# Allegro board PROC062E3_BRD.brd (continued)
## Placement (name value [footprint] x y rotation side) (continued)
NOREF#13  -  [#2]  213.87 20.07 0 top
NOREF#14  -  [unnamed]  206.38 143.51 0 top
NOREF#15  -  [unnamed]  3.49 4.19 0 top
NOREF#16  -  [unnamed]  10.79 72.99 0 top
NOREF#17  -  [#2]  -497.2 -71.75 0 top
NOREF#18  -  [#2]  11.81 0 90 top
NOREF#19  -  [unnamed]  87.71 3.81 0 top
NOREF#20  -  [#2]  98.62 -83.11 0 top
NOREF#21  -  [unnamed]  10.79 7.62 0 top
NOREF#22  -  [#2]  38.73 -95.89 0 top
NOREF#23  -  [unnamed]  206.38 170.05 0 top
NOREF#24  -  [unnamed]  164.53 143.51 0 top
NOREF#25  -  [unnamed]  206.38 106.68 0 top
NOREF#26  -  [unnamed]  213.68 4.19 0 top
NOREF#27  -  [#2]  330.6 97.43 0 top
NOREF#28  -  [unnamed]  146.43 43.18 0 top
NOREF#29  -  [unnamed]  3.49 9.14 0 top
NOREF#30  -  [unnamed]  192.15 26.04 0 top
NOREF#31  -  [unnamed]  10.79 170.05 0 top
NOREF#32  -  [unnamed]  197.87 73.03 0 top
NOREF#33  -  [unnamed]  10.79 173.99 0 top
NOREF#34  -  [unnamed]  114.36 143.51 0 top
NOREF#35  -  [unnamed]  193.68 3.81 0 top
NOREF#36  -  [unnamed]  213.68 173.61 0 top
NOREF#37  -  [unnamed]  105.47 173.99 0 top
NOREF#38  -  [#2]  -123.44 -23.24 0 top
NOREF#39  -  [unnamed]  173.36 1.97 0 top
NOREF#40  -  [unnamed]  10.79 3.81 0 top
NOREF#41  -  [unnamed]  3.49 173.61 0 top
NOREF#42  -  [unnamed]  149.36 1.97 0 top
NOREF#43  -  [unnamed]  3.49 168.4 180 bottom
NOREF#44  -  [unnamed]  206.38 170.05 180 bottom
NOREF#45  -  [unnamed]  3.49 9.14 180 bottom
NOREF#46  -  [unnamed]  10.79 7.62 180 bottom
NOREF#47  -  [unnamed]  213.68 168.4 180 bottom
NOREF#48  -  [unnamed]  10.79 170.05 180 bottom
Q1  SUM60N10-17-E3  [D2PAK-3]  45.47 149.22 270 top
Q2  SUM60N10-17-E3  [D2PAK-3]  43.43 137.16 90 top
Q3  BSS138LT1G  [SOT23-123]  15.49 132.61 270 top
Q4  BSS138LT1G  [SOT23-123]  11.91 130.57 270 top
Q5  BSS138LT1G  [SOT23-123]  18.84 104.03 270 top
Q6  BSS138LT1G  [SOT23-123]  22.99 76.58 180 top
Q7  IRLML6401  [TO_SOT23-123]  107.13 30.26 180 top
Q8  BSS138  [TO_SOT23-123]  22.86 166.62 90 bottom
Q9  BSS138LT1G  [SOT23-123]  12.41 109.37 0 bottom
Q10  BSS138LT1G  [SOT23-123]  72.12 107.13 90 bottom
Q11  BSS138LT1G  [SOT23-123]  63.46 103.25 90 bottom
Q12  BSS138LT1G  [SOT23-123]  25.48 99.46 270 bottom
Q13  BSS138LT1G  [SOT23-123]  21.67 99.45 270 bottom
Q14  BSS138LT1G  [SOT23-123]  13.31 93.93 0 bottom
Q15  BSS138LT1G  [SOT23-123]  21.73 84.35 180 bottom
Q16  BSS138LT1G  [SOT23-123]  13.49 88.97 0 bottom
Q17  BSS138LT1G  [SOT23-123]  22.99 76.58 180 bottom
R1  220E  [RES0402_0-5]  77.36 173.26 90 top
R2  1K  [RES0201]  85.66 173.16 90 top
R3  220E  [RES0402_0-5]  81.61 173.11 90 top
R4  1K  [RES0201]  143.92 173.61 0 top
R5  10K  [RES1206]  16.26 172.91 90 top
R6  10K  [RES0402_0-5]  127.25 168.77 270 top
R7  10K  [RES0402_0-5]  143.64 170.78 270 top
R8  10K  [RES0402_0-5]  136.82 170.43 0 top
R9  1K  [RES0201]  21.87 170.08 90 top
R10  0E  [RES0402_0-5]  138.37 170.01 270 top
R11  1K  [RES0201]  143.92 169.04 0 top
R12  100K  [RES0402_0-5]  165.23 168.31 90 top
R13  10K  [RES1206]  13.92 168.25 270 top
R14  0E  [RES0402_0-5]  156.27 167.68 0 top
R15  20.5K  [RES0402]  167.74 167.2 0 top
R16  10.2K_0.1%  [RES0402]  167.74 166.18 180 top
R17  1M  [RES0603_0-75]  12.8 166.09 180 bottom
R18  0E  [RES0402_0-5]  181.89 160.43 180 top
R19  10K  [RES0402_0-5]  155.58 158.96 90 top
R20  10K  [RES0402_0-5]  156.59 158.96 90 top
R21  10K  [RES0402_0-5]  157.61 158.96 270 top
R22  10K  [RES0402_0-5]  158.62 158.96 270 top
R23  10K  [RES0402_0-5]  159.64 158.96 270 top
R24  10K  [RES0402_0-5]  160.66 158.96 270 top
R25  16K_1%  [RES0402]  17.35 156.54 0 top
R26  10K  [RES0402_0-5]  136.39 156.51 180 top
R27  10K  [RES0402_0-5]  146.18 156.09 0 top
R28  76.8K_1%  [RES0402]  17.35 155.53 180 top
R29  10K  [RES0402_0-5]  136.39 155.5 180 top
R30  10K  [RES0402_0-5]  124.55 155.46 0 top
R31  10K_1%  [RES0402_0-5]  117.38 155.09 90 top
R32  10K  [RES0402_0-5]  124.55 154.48 0 top
R33  10K  [RES0402_0-5]  145.42 136.78 270 bottom
R34  23.2K_1%  [RES0402]  17.35 154.48 0 top
R35  10K_1%  [RES0402_0-5]  116.37 153.84 270 top
R36  10K  [RES0402_0-5]  136.39 154.14 180 top
R37  10K  [RES0402_0-5]  20.38 152.33 90 top
R38  10K  [RES0402_0-5]  159.26 149.86 180 top
R39  49.9E_1%  [RES0201]  135.86 149.95 180 top
R40  49.9E_1%  [RES0201]  137.22 149.95 0 top
R41  100K  [RES0402_0-5]  205.93 150.7 0 top
R42  10K_1%  [RES0402_0-5]  117.38 148.58 90 top
R43  39.2E_1%  [RES0402]  189.93 148.08 90 top
R44  39.2E_1%  [RES0402]  191.96 148.08 90 top
R45  39.2E_1%  [RES0402]  185.86 148.08 90 top
R46  39.2E_1%  [RES0402]  186.88 148.08 90 top
R47  39.2E_1%  [RES0402]  187.9 148.08 90 top
R48  39.2E_1%  [RES0402]  188.91 148.08 90 top
R49  39.2E_1%  [RES0402]  190.94 148.08 90 top
R50  10K  [RES0402_0-5]  20.38 147.97 90 top
R51  10K_1%  [RES0402_0-5]  116.37 147.33 270 top
R52  240E_1%  [RES0402]  181.5 145.16 180 top
R53  1K_1%  [RES0402_0-5]  81.47 144.65 180 top
R54  8.66K_1%  [RES0402]  81.47 143.64 0 top
R55  46.4K_1%  [RES0402]  78.74 142.88 0 top
R56  39.2E_1%  [RES0402]  195.07 142.75 0 top
R57  39.2E_1%  [RES0402]  195.07 141.73 0 top
R58  10K  [RES0402_0-5]  145.37 141.17 270 top
R59  49.9E_1%  [RES0201]  134.91 142.28 180 top
R60  49.9E_1%  [RES0201]  136.57 142.28 0 top
R61  39.2E_1%  [RES0402]  195.07 140.72 0 top
R62  0.028E_2%  [RES0815_0-75]  88.27 140.46 90 top
R63  39.2E_1%  [RES0402]  195.07 139.7 0 top
R64  10K_1%  [RES0402_0-5]  78.49 139.45 0 top
R65  18.2K_1%  [RES0402]  81.03 139.45 180 top
R66  10K  [RES0402_0-5]  157.29 139.13 180 top
R67  39.2E_1%  [RES0402]  195.07 138.68 0 top
R68  75K_1%  [RES0402_0-5]  78.49 138.43 180 top
R69  39.2E_1%  [RES0402]  195.07 136.65 0 top
R70  39.2E_1%  [RES0402]  195.07 135.64 0 top
R71  1M  [RES0603_0-75]  11.43 145.67 180 bottom
R72  0E  [RES0402_0-5]  12.44 132.84 180 top
R73  0E  [RES0402_0-5]  17.91 133.24 270 top
R74  0E  [RES0402_0-5]  122.11 129.54 0 top
R75  240E_1%  [RES0402]  181.5 131.44 180 top
R76  0E  [RES0402_0-5]  122.11 128.4 0 top
R77  1K  [RES0201]  8.36 130.2 90 top
R78  220E  [RES0402_0-5]  9.4 129.94 90 top
R79  220E  [RES0402_0-5]  15.91 129.67 0 top
R80  10K_1%  [RES0402_0-5]  113.28 127.87 90 top
R81  10K  [RES0402_0-5]  138.62 127.19 90 top
R82  10K  [RES0402_0-5]  139.64 127.19 270 top
R83  100K  [RES0402_0-5]  140.65 127.19 90 top
R84  1K  [RES0402]  141.67 127.19 270 top
R87  10K  [RES0402_0-5]  144.72 127.19 270 top
R88  10K  [RES0402_0-5]  145.73 127.19 90 top
R89  10K_1%  [RES0402_0-5]  112.28 126.62 270 top
R90  10K_1%  [RES0402_0-5]  33.27 123.44 270 top
R91  2.49K_1%  [RES0402]  34.29 123.44 90 top
R92  2.49K_1%  [RES0402]  35.31 123.44 90 top
R93  10K_1%  [RES0402_0-5]  36.32 123.44 270 top
R94  5.76K_1%  [RES0402]  37.47 123.44 270 top
R95  2.49K_1%  [RES0402]  38.48 123.44 90 top
R96  2.49K_1%  [RES0402]  39.5 123.44 90 top
R97  10K_1%  [RES0402_0-5]  40.51 123.44 270 top
R98  5.76K_1%  [RES0402]  41.53 123.44 90 top
R99  2.49K_1%  [RES0402]  42.55 123.44 90 top
R100  2.2K  [RES0402_0-5]  35.69 120.9 90 top
R101  22E_1%  [RES0402]  40.39 120.9 270 top
R102  22E_1%  [RES0402]  42.67 120.27 180 top
R103  220E  [RES0402_0-5]  48.01 119.89 270 top
R104  220E  [RES0402_0-5]  50.8 119.89 270 top
R105  220E  [RES0402_0-5]  53.57 119.89 270 top
R106  220E  [RES0402_0-5]  56.39 119.89 270 top
R107  220E  [RES0402_0-5]  59.05 119.89 270 top
R108  220E  [RES0402_0-5]  61.85 119.89 270 top
R109  220E  [RES0402_0-5]  64.77 119.89 270 top
R110  220E  [RES0402_0-5]  67.44 119.89 270 top
R111  22E_1%  [RES0402]  42.67 119.13 180 top
R112  2.49K_1%  [RES0402]  45.47 119.13 0 top
R113  10K_1%  [RES0402_0-5]  108.82 119.09 180 top
R114  22E_1%  [RES0402]  42.67 118.11 180 top
R115  2.49K_1%  [RES0402]  45.47 118.11 180 top
R116  10K_1%  [RES0402_0-5]  110.07 118.08 0 top
R117  240E_1%  [RES0402]  181.5 117.73 180 top
R118  22E_1%  [RES0402]  42.67 116.97 180 top
R119  2.49K_1%  [RES0402]  45.47 116.97 180 top
R120  10K  [RES0402_0-5]  108.01 116.03 0 top
R121  22E_1%  [RES0402]  42.67 115.95 180 top
R122  2.49K_1%  [RES0402]  45.47 115.95 0 top
R123  10K  [RES0402_0-5]  105.6 115.57 0 top
R124  10K  [RES0402_0-5]  96.18 115.49 180 top
R125  10K  [RES0402_0-5]  108.01 115.05 180 top
R126  10K  [RES0402_0-5]  105.6 114.55 0 top
R127  10K  [RES0402_0-5]  96.18 114.49 180 top
R128  33E_1%  [RES0402_0-5]  139.45 114.43 90 top
R129  0E  [RES0402_0-5]  140.46 114.43 90 top
R130  4.7K  [RES0402]  141.48 114.43 90 top
R131  33E_1%  [RES0402_0-5]  144.21 114.43 270 top
R132  22E_1%  [RES0402]  150.81 114.36 270 top
R133  10K  [RES0402_0-5]  105.6 113.54 0 top
R134  10K  [RES0402_0-5]  92.03 112.72 270 top
R135  11K_1%  [RES0402_0-5]  31.88 112.64 180 top
R136  100K  [RES0402_0-5]  105.6 112.52 0 top
R137  10K_1%  [RES0402_0-5]  48.13 110.29 270 top
R138  2.49K_1%  [RES0402]  49.15 110.29 90 top
R139  2.49K_1%  [RES0402]  50.16 110.29 90 top
R140  10K_1%  [RES0402_0-5]  51.18 110.29 270 top
R141  5.76K_1%  [RES0402]  52.2 110.29 270 top
R142  2.49K_1%  [RES0402]  53.21 110.29 90 top
R143  2.49K_1%  [RES0402]  54.23 110.29 90 top
R144  10K_1%  [RES0402_0-5]  55.24 110.29 270 top
R145  5.76K_1%  [RES0402]  56.26 110.29 90 top
R146  2.49K_1%  [RES0402]  57.28 110.29 90 top
R147  10K_1%  [RES0402_0-5]  110.3 109.06 180 top
R148  0E  [RES0402_0-5]  111.84 108.64 90 top
R149  10K  [RES0201]  32.28 108.03 270 top
R150  10K  [RES0402_0-5]  31.24 107.82 270 top
R151  2.2K  [RES0402_0-5]  50.42 107.75 90 top
R152  22E_1%  [RES0402]  55.12 107.75 270 top
R153  10K  [RES0402_0-5]  99.35 107.53 180 top
R154  22E_1%  [RES0402]  57.4 107.12 180 top
R155  220E  [RES0402_0-5]  71.04 106.81 90 top
R156  10K  [RES0201]  35.91 106.17 0 top
R157  22E_1%  [RES0402]  57.4 105.97 180 top
R158  2.49K_1%  [RES0402]  60.2 105.97 0 top
R159  10K  [RES0402_0-5]  105.34 105.63 0 top
R160  10K  [RES0402_0-5]  35.91 105.15 0 top
R161  0E  [RES0402_0-5]  21.77 105.08 0 top
R162  22E_1%  [RES0402]  57.4 104.96 180 top
R163  2.49K_1%  [RES0402]  60.2 104.96 180 top
R164  10K  [RES0402_0-5]  29.34 104.65 0 top
R165  0E  [RES0402_0-5]  164.21 104.39 180 top
R166  240E_1%  [RES0402]  181.5 104.01 180 top
R167  2.49K_1%  [RES0402]  60.2 103.94 180 top
R168  22E_1%  [RES0402]  57.4 103.82 180 top
R169  22E_1%  [RES0402]  72.64 103.38 90 top
R170  22E_1%  [RES0402]  73.66 103.38 90 top
R171  0E  [RES0402_0-5]  164.21 103.38 180 top
R172  1K  [RES0201]  76.05 103.37 90 top
R173  1K  [RES0201]  77.58 103.37 270 top
R174  10K  [RES0201]  37.51 103.25 0 top
R175  10K  [RES0201]  32.57 103.96 180 bottom
R176  10K  [RES0402_0-5]  91.23 103.06 270 top
R177  220E  [RES0402_0-5]  64.58 102.99 90 top
R178  220E  [RES0402_0-5]  15.88 102.98 180 top
R179  2.49K_1%  [RES0402]  60.2 102.93 0 top
R180  0E  [RES0402_0-5]  118.45 102.87 180 top
R181  22E_1%  [RES0402]  57.4 102.8 180 top
R182  2.2K  [RES0402_0-5]  164.21 102.36 0 top
R183  0E  [RES0402_0-5]  118.45 101.85 180 top
R184  100E  [RES0402_0-5]  107.38 101.77 90 top
R185  100E  [RES0402_0-5]  75.78 100.62 270 top
R186  240E_1%  [RES0402]  164.21 100.33 0 top
R187  10K  [RES0402_0-5]  66.8 100.09 0 top
R188  11K_1%  [RES0402_0-5]  46.61 99.49 180 top
R189  10K  [RES0402_0-5]  66.8 99.07 180 top
R190  100E  [RES0402_0-5]  76.2 99.06 0 top
R191  0E  [RES0402_0-5]  78.17 98.78 180 top
R192  1M_1%  [RES0402]  79.69 98.18 90 top
R193  10K  [RES0402_0-5]  66.8 98.06 180 top
R194  0E  [RES0402_0-5]  78.17 97.57 180 top
R195  0E  [RES0402_0-5]  107.37 97.39 270 top
R196  10E_1%  [RES0402_0-5]  96.39 97.35 0 top
R197  10K  [RES0402_0-5]  66.8 97.04 0 top
R198  2.2K  [RES0402_0-5]  50.16 97.03 180 top
R199  10K  [RES0402_0-5]  66.8 96.02 180 top
R200  261K_1%  [RES0402_0-5]  89.93 95.4 270 top
R201  10K_1%  [RES0402_0-5]  90.95 95.4 90 top
R202  10E_1%  [RES0402_0-5]  96.1 95 180 top
R203  22E_1%  [RES0402]  68.45 94.11 270 top
R204  22E_1%  [RES0402]  71.12 94.11 270 top
R205  22E_1%  [RES0402]  72.14 94.11 270 top
R206  22E_1%  [RES0402]  73.15 94.11 270 top
R207  22E_1%  [RES0402]  74.17 94.11 270 top
R208  22E_1%  [RES0402]  164.13 92.7 0 top
R209  22E_1%  [RES0402]  131.64 92.08 180 top
R210  10K_1%  [RES0402_0-5]  94.11 91.48 180 top
R211  22E_1%  [RES0402]  131.64 91.06 180 top
R212  240E_1%  [RES0402]  181.5 90.3 180 top
R213  4.7K  [RES0402]  96.52 90.04 0 top
R214  4.7K  [RES0402]  89.28 89.15 270 top
R215  10K  [RES0402_0-5]  85.05 83.79 270 top
R216  10K  [RES0402_0-5]  86.07 83.79 270 top
R217  4.7K  [RES0402]  88.27 82.74 90 top
R218  10K  [RES0402_0-5]  89.28 82.74 270 top
R219  2.2K  [RES0402_0-5]  193.84 80.79 180 top
R220  2.2K  [RES0402_0-5]  193.84 79.77 0 top
R221  10K  [RES0402_0-5]  95.95 79.18 180 top
R222  100E  [RES0402_0-5]  95.95 78.17 180 top
R223  33E_1%  [RES0402_0-5]  102.55 77.14 180 top
R224  220E  [RES0402_0-5]  14.86 76.24 270 top
R225  0E  [RES0402_0-5]  26.16 75.63 0 top
R227  10K  [RES0402_0-5]  95.95 75.12 180 top
R228  100K  [RES0402_0-5]  26.16 74.62 180 top
R229  100E  [RES0402_0-5]  95.95 74.1 180 top
R230  100K  [RES0402_0-5]  28.83 73.85 270 top
R231  1K  [RES0201]  25.95 73.66 0 top
R232  1K  [RES0201]  27.88 73.65 90 top
R233  33E_1%  [RES0402_0-5]  102.55 73.15 180 top
R234  0.01E_0.5%  [RES1206-4TERM_0-75]  184.48 70.41 90 top
R235  10K  [RES0402_0-5]  86.35 66.67 90 top
R236  10K  [RES0402_0-5]  87.37 66.67 90 top
R237  10K  [RES0402_0-5]  88.39 66.67 90 top
R238  10K  [RES0402_0-5]  89.4 66.67 90 top
R239  1K  [RES0201]  118.76 65.47 0 top
R240  100K  [RES0402_0-5]  131.46 65.47 0 top
R241  22E_1%  [RES0402]  115.34 64.99 0 top
R242  1K  [RES0201]  137.65 64.21 0 top
R243  100K  [RES0402_0-5]  149.42 64.21 0 top
R244  1K  [RES0201]  118.76 64.2 0 top
R245  100K  [RES0402_0-5]  131.46 64.2 0 top
R246  10K  [RES0402_0-5]  188.85 58.8 180 bottom
R247  10K  [RES0402_0-5]  177.42 63.56 0 top
R248  1K  [RES0201]  137.65 62.94 0 top
R249  100K  [RES0402_0-5]  149.42 62.94 0 top
R250  1K  [RES0201]  118.76 62.93 0 top
R251  100K  [RES0402_0-5]  131.46 62.93 0 top
R252  10K  [RES0402_0-5]  157.73 62.87 90 top
R253  22E_1%  [RES0402]  158.75 62.87 270 top
R254  10K  [RES0402_0-5]  114.53 62.76 180 top
R255  10K  [RES0402_0-5]  170.94 62.61 0 top
R256  10K  [RES0402_0-5]  177.42 62.55 180 top
R257  1K  [RES0201]  137.65 61.67 0 top
R258  100K  [RES0402_0-5]  149.42 61.67 0 top
R259  1K  [RES0201]  118.76 61.66 0 top
R260  100K  [RES0402_0-5]  131.46 61.66 0 top
R261  10K  [RES0402_0-5]  170.94 61.6 0 top
R262  49.9K_1%  [RES0402]  156.78 60.64 270 top
R263  49.9K_1%  [RES0402]  157.92 60.64 270 top
R264  49.9K_1%  [RES0402]  159.07 60.64 270 top
R265  49.9K_1%  [RES0402]  160.21 60.64 270 top
R266  49.9K_1%  [RES0402]  161.35 60.64 270 top
R267  49.9K_1%  [RES0402]  162.5 60.64 270 top
R268  49.9K_1%  [RES0402]  163.64 60.64 270 top
R269  49.9K_1%  [RES0402]  164.78 60.64 270 top
R270  10K  [RES0402_0-5]  190.61 54.86 0 bottom
R271  1K  [RES0201]  137.65 60.4 0 top
R272  100K  [RES0402_0-5]  149.42 60.4 0 top
R273  1K  [RES0201]  118.76 60.39 0 top
R274  100K  [RES0402_0-5]  131.46 60.39 0 top
R275  1K  [RES0201]  137.65 59.13 0 top
R276  100K  [RES0402_0-5]  149.42 59.13 0 top
R277  1K  [RES0201]  118.76 59.12 0 top
R278  100K  [RES0402_0-5]  131.46 59.12 0 top
R279  1K  [RES0201]  137.65 57.86 0 top
R280  100K  [RES0402_0-5]  149.42 57.86 0 top
R281  1K  [RES0201]  118.76 57.85 0 top
R282  100K  [RES0402_0-5]  131.46 57.85 0 top
R283  10K  [RES0402_0-5]  89.4 56.64 270 top
R284  1K  [RES0201]  137.65 56.59 0 top
R285  100K  [RES0402_0-5]  149.42 56.59 0 top
R286  1K  [RES0201]  118.76 56.58 0 top
R287  100K  [RES0402_0-5]  131.46 56.58 0 top
R288  10K  [RES0402_0-5]  154.52 55.88 90 top
R289  10K_1%  [RES0402_0-5]  114.35 55.37 270 top
R290  1K  [RES0201]  137.65 55.32 0 top
R291  100K  [RES0402_0-5]  149.42 55.32 0 top
R292  1K  [RES0201]  118.76 55.31 0 top
R293  100K  [RES0402_0-5]  131.46 55.31 0 top
R294  1K  [RES0201]  137.65 54.05 0 top
R295  100K  [RES0402_0-5]  149.42 54.05 0 top
R296  1K  [RES0201]  118.76 54.04 0 top
R297  100K  [RES0402_0-5]  131.46 54.04 0 top
R299  0E  [RES0402_0-5]  106.21 50.55 180 top
R300  10K_1%  [RES0402_0-5]  114.31 50.48 270 top
R301  100K  [RES0402_0-5]  127.89 50.2 180 top
R302  1K  [RES0201]  137.45 50.2 180 top
R303  10K  [RES0402_0-5]  152.62 50.04 270 top
R304  10K  [RES0402_0-5]  153.57 50.04 270 top
R305  100K  [RES0402_0-5]  127.89 48.93 180 top
R306  1K  [RES0201]  137.45 48.93 180 top
R307  10K  [RES0402_0-5]  88.86 42.87 0 top
R308  10K  [RES0402_0-5]  106.91 42.61 0 top
R309  10K  [RES0402_0-5]  113.34 41.4 90 top
R310  10K  [RES0402_0-5]  178.18 37.69 0 top
R311  0E  [RES0402_0-5]  163.54 37.43 270 top
R312  1K  [RES0201]  57.85 34.73 270 top
R313  1K  [RES0201]  58.86 34.73 90 top
R314  1K  [RES0201]  59.88 34.73 90 top
R315  1K  [RES0201]  60.9 34.73 270 top
R316  0E  [RES0402_0-5]  190.46 33.72 90 top
R317  0E  [RES0402_0-5]  191.54 33.72 90 top
R318  10K  [RES0402_0-5]  139.26 32.23 270 top
R319  10K  [RES0402_0-5]  108.32 33.02 90 top
R320  10K  [RES0402_0-5]  154.74 32.3 270 top
R321  10K  [RES0402_0-5]  123.76 33.07 90 top
R322  10K  [RES0402_0-5]  64.83 27.43 0 top
R323  100E  [RES0402_0-5]  63.44 26.92 270 top
R324  10K  [RES0402_0-5]  64.83 26.42 0 top
R325  0E  [RES0402_0-5]  111 24.9 180 top
R326  0E  [RES0402_0-5]  111 22.36 180 top
R327  10K  [RES0402_0-5]  176.47 18.48 0 top
R328  10K  [RES0402_0-5]  176.47 17.46 0 top
R329  10K  [RES0402_0-5]  186.88 17.28 180 top
R330  10K  [RES0402_0-5]  176.47 16.45 0 top
R331  10K  [RES0402_0-5]  176.47 15.43 0 top
R332  220E  [RES0402_0-5]  97.74 13.65 0 top
R333  30K  [RES0402_0-5]  109.43 11.24 90 top
R334  51K  [RES0402_0-5]  111.12 10.4 90 top
R335  180E  [RES0402]  97.74 8.32 0 top
R336  10K  [RES0402_0-5]  154.56 170.61 270 bottom
R337  4.7K  [RES0402]  65.71 170.55 270 bottom
R338  0E  [RES0402_0-5]  59.78 168.94 0 bottom
R339  40.2K_1%  [RES0402_0-5]  141.73 167.7 90 bottom
R340  60.4K_1%  [RES0402_0-5]  140.72 167.7 270 bottom
R341  0E  [RES0402_0-5]  139.57 167.7 270 bottom
R342  0.01E_0.5%  [RES1206-4TERM_0-75]  155.84 165.08 270 bottom
R343  158K_1%  [RES0402_0-5]  111.06 164.98 180 bottom
R344  40.2K_1%  [RES0402_0-5]  111.06 163.97 0 bottom
R345  499K_1%  [RES0402]  112.65 162.47 90 bottom
R346  10K_1%  [RES0402_0-5]  23.39 161.8 0 bottom
R347  100K  [RES0402_0-5]  21.48 161.8 180 bottom
R348  0.002E_1%  [RES2512-4TERM_0-75]  185.21 160.41 180 bottom
R349  0.01E_0.5%  [RES1206-4TERM_0-75]  149.89 158.45 180 bottom
R350  47K _1%  [RES0402_0-5]  29.1 157.69 90 bottom
R351  237K_1%  [RES0402]  28.08 157.69 270 bottom
R352  100K  [RES0402_0-5]  27.07 157.67 270 bottom
R353  47K _1%  [RES0402_0-5]  25.92 157.67 90 bottom
R354  665K_1%  [RES0603_0-5]  24.53 157.28 270 bottom
R355  0.002E_1%  [RES2512-4TERM_0-75]  131.93 157.19 0 bottom
R356  10K  [RES0402_0-5]  124.55 155.46 0 bottom
R357  0.005E  [RES1206]  86.33 156.27 0 bottom
R358  0E  [RES0402_0-5]  153.85 153.85 0 bottom
R359  0E  [RES0402_0-5]  33.66 153.54 180 bottom
R360  0.01E_0.5%  [RES1206-4TERM_0-75]  175.4 153.75 180 bottom
R361  0.01E_0.5%  [RES1206-4TERM_0-75]  164.87 153.37 180 bottom
R362  5.62k_1%  [RES0603]  26.37 151.59 0 bottom
R363  0E  [RES0402_0-5]  136.6 151.19 0 bottom
R364  0E  [RES0402_0-5]  179.24 149.02 0 bottom
R365  0E  [RES0402_0-5]  168.95 148.77 0 bottom
R366  39.2E_1%  [RES0402]  191.96 148.08 90 bottom
R367  39.2E_1%  [RES0402]  190.94 148.08 90 bottom
R368  39.2E_1%  [RES0402]  189.93 148.08 90 bottom
R369  39.2E_1%  [RES0402]  188.91 148.08 90 bottom
R370  39.2E_1%  [RES0402]  187.9 148.08 90 bottom
R371  39.2E_1%  [RES0402]  186.88 148.08 90 bottom
R372  39.2E_1%  [RES0402]  185.86 148.08 90 bottom
R373  39.2E_1%  [RES0402]  184.85 148.08 90 bottom
R374  39.2E_1%  [RES0402]  183.83 148.08 90 bottom
R375  19.6K_0.1%  [RES0402]  105.54 144.53 90 bottom
R376  100K  [RES0402_0-5]  100.97 149.22 0 bottom
R377  39.2E_1%  [RES0402]  195.07 142.75 0 bottom
R378  10.2E_1%  [RES0402_0-5]  101.41 142.05 270 bottom
R379  39.2E_1%  [RES0402]  195.07 141.73 0 bottom
R380  16K_1%  [RES0402]  145.9 144.5 0 bottom
R381  10K_1%  [RES0402_0-5]  17.1 141.22 270 bottom
R382  39.2E_1%  [RES0402]  195.07 140.72 0 bottom
R383  39.2E_1%  [RES0402]  195.07 139.7 0 bottom
R384  10.2E_1%  [RES0402_0-5]  83.06 142.63 0 top
R385  10K  [RES0402_0-5]  163.77 139.13 0 bottom
R386  39.2E_1%  [RES0402]  195.07 138.68 0 bottom
R387  10.2E_1%  [RES0402_0-5]  83.06 141.36 0 top
R388  12K_1%  [RES0402]  19.11 137.69 0 bottom
R389  39.2E_1%  [RES0402]  195.07 137.67 0 bottom
R390  10K  [RES0402_0-5]  157.29 137.23 180 bottom
R391  39.2E_1%  [RES0402]  195.07 136.65 0 bottom
R392  10.2E_1%  [RES0402_0-5]  82.99 128.78 90 top
R393  39.2E_1%  [RES0402]  195.07 135.64 0 bottom
R394  10K  [RES0402_0-5]  132.65 135.31 90 bottom
R395  10K  [RES0402_0-5]  127.57 135.31 270 bottom
R396  10.2E_1%  [RES0402_0-5]  84.26 128.78 90 top
R397  0E  [RES0402_0-5]  122.11 129.54 180 bottom
R398  100K  [RES0402_0-5]  149.61 133.43 0 bottom
R399  29.4K_1%  [RES0402]  104.65 131.38 0 bottom
R400  0E  [RES0402_0-5]  122.11 128.4 180 bottom
R401  100K  [RES0402_0-5]  43.43 131.06 0 bottom
R402  10K  [RES0402_0-5]  140.59 130.83 180 bottom
R403  10K  [RES0402_0-5]  149.61 130.81 0 bottom
R404  100K  [RES0402_0-5]  102.74 130.75 0 bottom
R405  10.2E_1%  [RES0402_0-5]  100.97 130.75 0 bottom
R406  10K  [RES0402_0-5]  140.59 129.68 180 bottom
R407  2.2K  [RES0402_0-5]  24.38 129.79 0 bottom
R408  10K  [RES0402_0-5]  25.27 131.32 90 bottom
R409  10K  [RES0402_0-5]  39.12 129.35 180 bottom
R410  22E_1%  [RES0402]  149.24 129.15 270 bottom
R411  10K  [RES0402_0-5]  140.59 128.67 180 bottom
R412  10K  [RES0402_0-5]  39.12 128.33 0 bottom
R413  10K  [RES0402_0-5]  24.38 128.14 180 bottom
R414  2.05K_1%  [RES0402]  43.37 127.19 180 bottom
R415  10K  [RES0402_0-5]  39.12 127.25 0 bottom
R416  10K  [RES0402_0-5]  24.38 127 180 bottom
R417  10K  [RES0402_0-5]  33.15 126.43 180 bottom
R418  10K_1%  [RES0402_0-5]  46.23 125.39 90 bottom
R419  51.1E_1%  [RES0402_0-5]  43.18 125.35 270 bottom
R420  10K  [RES0402_0-5]  148.21 125.29 270 bottom
R421  10K  [RES0402_0-5]  147.07 125.29 270 bottom
R422  10K  [RES0402_0-5]  145.92 125.29 270 bottom
R423  10K  [RES0402_0-5]  144.84 125.29 270 bottom
R424  10K  [RES0402_0-5]  143.7 125.29 270 bottom
R425  31.6K_1%  [RES0402]  44.7 124.97 0 bottom
R426  0.005E  [RES1206]  86.16 119.81 180 bottom
R427  10K  [RES0402_0-5]  154.19 120.55 90 bottom
R428  10K  [RES0402_0-5]  140.65 120.32 90 bottom
R429  0E  [RES0402_0-5]  148.21 120.14 90 bottom
R430  22E_1%  [RES0402]  142.3 120.14 90 bottom
R431  10K  [RES0402_0-5]  67.1 117.36 180 bottom
R432  22E_1%  [RES0402]  142.96 115.89 0 bottom
R438  22E_1%  [RES0402]  149.42 115.57 90 bottom
R439  22E_1%  [RES0402]  148.4 115.57 90 bottom
R440  10K  [RES0402_0-5]  108.01 115.05 180 bottom
R441  10K  [RES0402_0-5]  143.8 114.88 0 bottom
R442  10K  [RES0402_0-5]  142.96 114.88 0 bottom
R447  10K_1%  [RES0402_0-5]  84.75 110.26 0 bottom
R448  22E_1%  [RES0402]  130.3 110.05 0 bottom
R449  220E  [RES0402_0-5]  15.49 109.98 90 bottom
R450  0E  [RES0402_0-5]  130.3 108.9 180 bottom
R451  0E  [RES0402_0-5]  10.1 108.84 90 bottom
R452  10K_1%  [RES0402_0-5]  85.85 108.65 180 bottom
R453  10K  [RES0402_0-5]  66.59 108.39 90 bottom
R454  10K  [RES0402_0-5]  67.86 108.36 90 bottom
R455  1M_1%  [RES0402]  128.65 108.3 270 bottom
R456  1M  [RES0603_0-75]  21.21 108.34 270 bottom
R457  0E  [RES0402_0-5]  130.3 107.7 180 bottom
R458  0E  [RES0402_0-5]  74.35 106.5 90 bottom
R459  0.002E_1%  [RES2512-4TERM_0-75]  114.68 106.81 0 bottom
R460  10K  [RES0402_0-5]  190.18 104.58 270 bottom
R462  1K  [RES0201]  185.93 102.93 180 bottom
R463  0E  [RES0402_0-5]  118.45 102.87 180 bottom
R464  0E  [RES0402_0-5]  65.86 102.62 90 bottom
R466  0E  [RES0402_0-5]  118.45 101.85 180 bottom
R467  0E  [RES0402_0-5]  24.94 101.73 0 bottom
R468  0E  [RES0402_0-5]  21.14 101.73 0 bottom
R469  76.8K_1%  [RES0402]  123.63 101.09 0 bottom
R470  10E_1%  [RES0402_0-5]  95.69 100.55 0 bottom
R471  23.2K_1%  [RES0402]  123.63 100.08 180 bottom
R472  10E_1%  [RES0402_0-5]  95.69 99.47 0 bottom
R473  1M  [RES0603_0-75]  12.42 103.39 90 bottom
R474  0E  [RES0402_0-5]  123.63 99.06 0 bottom
R475  10E_1%  [RES0402_0-5]  95.69 98.39 0 bottom
R476  6.81K_1%  [RES0402_0-5]  172.53 98.3 0 bottom
R477  0E  [RES0402_0-5]  123.63 98.04 180 bottom
R478  0E  [RES0402_0-5]  107.37 97.39 270 bottom
R479  100E  [RES0402_0-5]  95.69 97.31 0 bottom
R481  220E  [RES0402_0-5]  25.9 97.16 0 bottom
R482  220E  [RES0402_0-5]  22.09 97.16 0 bottom
R483  3K_1%  [RES0402_0-5]  123.63 97.03 180 bottom
R484  10K_1%  [RES0402_0-5]  123.63 96.01 180 bottom
R486  40.2K_1%  [RES0402_0-5]  123.63 95 0 bottom
R489  22E_1%  [RES0402]  123.63 93.98 0 bottom
R490  220E  [RES0402_0-5]  15.75 93.51 270 bottom
R491  22E_1%  [RES0402]  123.63 92.96 0 bottom
R494  22E_1%  [RES0402]  123.63 91.95 180 bottom
R495  0E  [RES0402_0-5]  12.68 91.57 0 bottom
R496  220E  [RES0402_0-5]  16.17 89.79 0 bottom
R497  3K_1%  [RES0402_0-5]  123.63 90.93 180 bottom
R498  2.2K  [RES0402_0-5]  50.16 89.98 180 bottom
R499  22E_1%  [RES0402]  130.11 89.92 180 bottom
R500  22E_1%  [RES0402]  123.63 89.92 180 bottom
R501  220E  [RES0402_0-5]  16.17 91 0 bottom
R503  1K  [RES0201]  185.86 89.34 90 bottom
R504  4.7K  [RES0402]  92.9 89.15 270 bottom
R505  22E_1%  [RES0402]  130.11 88.9 180 bottom
R506  10K  [RES0402_0-5]  70.68 88.63 0 bottom
R507  0E  [RES0402_0-5]  165.8 87.99 0 bottom
R508  22E_1%  [RES0402]  130.11 87.88 180 bottom
R509  11K_1%  [RES0402_0-5]  46.61 87.52 180 bottom
R510  1M_1%  [RES0402]  167.39 87.48 270 bottom
R511  0E  [RES0402_0-5]  165.8 86.98 0 bottom
R512  0E  [RES0402_0-5]  12.86 86.61 180 bottom
R513  10K  [RES0402_0-5]  70.68 86.73 0 bottom
R514  10K  [RES0402_0-5]  64.83 86.73 180 bottom
R515  0E  [RES0402_0-5]  23.2 86.74 180 bottom
R516  10K  [RES0402_0-5]  183.2 86.3 0 bottom
R517  22E_1%  [RES0402]  57.4 84.21 180 bottom
R518  2.49K_1%  [RES0402]  60.2 84.08 0 bottom
R519  22E_1%  [RES0402]  57.4 83.19 180 bottom
R520  2.49K_1%  [RES0402]  60.2 83.07 180 bottom
R521  4.7K  [RES0402]  93.03 83.06 90 bottom
R522  2.49K_1%  [RES0402]  60.2 82.05 180 bottom
R523  22E_1%  [RES0402]  57.4 82.05 180 bottom
R524  2.49K_1%  [RES0402]  60.2 81.03 0 bottom
R525  22E_1%  [RES0402]  57.4 81.03 180 bottom
R526  10K  [RES0402_0-5]  144.4 80.71 0 bottom
R527  22E_1%  [RES0402]  140.34 80.39 270 bottom
R528  22E_1%  [RES0402]  139.32 80.39 270 bottom
R532  22E_1%  [RES0402]  166.12 72.45 270 bottom
R533  22E_1%  [RES0402]  165.1 72.45 270 bottom
R534  22E_1%  [RES0402]  164.08 72.45 90 bottom
R535  10K  [RES0402_0-5]  158.24 80.07 270 bottom
R536  10K  [RES0402_0-5]  157.23 80.07 270 bottom
R537  22E_1%  [RES0402]  57.4 79.89 180 bottom
R538  4.7K  [RES0402]  123.63 79.69 0 bottom
R539  10K  [RES0402_0-5]  144.4 79.69 0 bottom
R540  1K  [RES0201]  25.96 79.56 0 bottom
R541  22E_1%  [RES0402]  55.12 79.26 90 bottom
R542  2.2K  [RES0402_0-5]  50.42 79.26 270 bottom
R543  33E_1%  [RES0402_0-5]  102.55 79.04 180 bottom
R544  10K  [RES0402_0-5]  150.62 78.74 180 bottom
R545  4.7K  [RES0402]  123.63 78.68 0 bottom
R546  100K  [RES0402_0-5]  26.16 78.55 180 bottom
R547  10K  [RES0402_0-5]  150.62 77.72 180 bottom
R548  0E  [RES0402_0-5]  26.16 77.53 0 bottom
R549  100K  [RES0402_0-5]  33.8 77.3 180 bottom
R550  0E  [RES0402_0-5]  83.57 78.17 180 bottom
R551  0E  [RES0402_0-5]  93.85 77.49 270 bottom
R552  10K  [RES0402_0-5]  92.84 77.49 270 bottom
R553  2.49K_1%  [RES0402]  57.28 76.72 270 bottom
R554  5.76K_1%  [RES0402]  56.26 76.72 270 bottom
R555  10K_1%  [RES0402_0-5]  55.24 76.72 90 bottom
R556  2.49K_1%  [RES0402]  54.23 76.72 270 bottom
R557  2.49K_1%  [RES0402]  53.21 76.72 270 bottom
R558  5.76K_1%  [RES0402]  52.2 76.72 90 bottom
R559  10K_1%  [RES0402_0-5]  51.18 76.72 90 bottom
R560  2.49K_1%  [RES0402]  50.16 76.72 270 bottom
R561  2.49K_1%  [RES0402]  49.15 76.72 270 bottom
R562  10K_1%  [RES0402_0-5]  48.13 76.72 90 bottom
R563  1M_1%  [RES0402]  81.92 77.53 90 bottom
R564  0E  [RES0402_0-5]  83.57 76.9 180 bottom
R565  33E_1%  [RES0402_0-5]  102.55 75.05 180 bottom
R566  18.7E_1%  [RES0402]  34.86 74.74 90 bottom
R567  8.87E_1%  [RES0402]  33.84 74.72 270 bottom
R568  22E_1%  [RES0402]  148.78 74.36 270 bottom
R569  0E  [RES0402_0-5]  147.76 74.36 270 bottom
R570  22E_1%  [RES0402]  146.75 74.36 270 bottom
R571  0E  [RES0402_0-5]  145.73 74.36 270 bottom
R572  0E  [RES0402_0-5]  144.72 74.36 270 bottom
R573  0E  [RES0402_0-5]  143.7 74.36 270 bottom
R574  0E  [RES0402_0-5]  142.68 74.36 270 bottom
R575  0E  [RES0402_0-5]  141.67 74.36 270 bottom
R576  0E  [RES0402_0-5]  140.65 74.36 270 bottom
R577  0E  [RES0402_0-5]  139.64 74.36 270 bottom
R578  0E  [RES0402_0-5]  138.62 74.36 270 bottom
R579  0E  [RES0402_0-5]  137.6 74.36 270 bottom
R580  0E  [RES0402_0-5]  136.59 74.36 270 bottom
R581  4.7K  [RES0402]  163.89 66.61 90 bottom
R582  4.7K  [RES0402]  162.88 66.61 90 bottom
R583  4.7K  [RES0402]  161.86 66.61 90 bottom
R584  4.7K  [RES0402]  160.85 66.61 90 bottom
R585  4.7K  [RES0402]  159.83 66.61 90 bottom
R586  4.7K  [RES0402]  158.81 66.61 90 bottom
R587  0E  [RES0402_0-5]  156.58 74.23 270 bottom
R588  0E  [RES0402_0-5]  155.46 74.23 270 bottom
R589  0E  [RES0402_0-5]  154.34 74.23 270 bottom
R590  0E  [RES0402_0-5]  153.23 74.23 270 bottom
R591  0E  [RES0402_0-5]  182.75 66.93 0 bottom
R592  4.7K  [RES0402]  185.25 66.55 90 bottom
R593  4.7K  [RES0402]  184.24 66.55 90 bottom
R594  100E  [RES0201]  202.37 47.37 180 bottom
R595  100E  [RES0201]  200.72 47.41 180 bottom
R596  10K  [RES0402_0-5]  142.09 65.9 180 bottom
R597  100E  [RES0201]  198.78 47.41 180 bottom
R598  100E  [RES0201]  199.2 20.43 90 bottom
R599  100E  [RES0201]  196.85 47.41 0 bottom
R600  10K  [RES0402_0-5]  186.92 64.17 180 bottom
R601  1K  [RES0201]  147.34 63.93 180 bottom
R602  1K  [RES0201]  147.34 62.91 180 bottom
R603  1K  [RES0201]  147.34 61.9 180 bottom
R604  10K  [RES0402_0-5]  188.03 60.47 0 bottom
R605  10K  [RES0402_0-5]  83.32 58.86 180 bottom
R606  10K  [RES0402_0-5]  174.62 57.06 270 bottom
R607  10K  [RES0402_0-5]  173.61 57.06 270 bottom
R608  10K  [RES0402_0-5]  176.28 56.12 0 bottom
R609  0E  [RES0402_0-5]  44.51 56.11 180 bottom
R610  0E  [RES0402_0-5]  42.99 55.48 90 bottom
R611  0E  [RES0402_0-5]  41.72 55.48 90 bottom
R612  0E  [RES0402_0-5]  39.18 55.48 90 bottom
R613  0E  [RES0402_0-5]  37.91 55.48 90 bottom
R614  10K  [RES0402_0-5]  176.28 55.1 0 bottom
R615  0E  [RES0402_0-5]  44.51 55.1 180 bottom
R616  10K  [RES0402_0-5]  176.28 54.09 0 bottom
R617  0E  [RES0402_0-5]  42.99 53.7 270 bottom
R618  0E  [RES0402_0-5]  41.72 53.7 270 bottom
R619  0E  [RES0402_0-5]  39.18 53.7 270 bottom
R620  0E  [RES0402_0-5]  37.91 53.7 270 bottom
R621  10K  [RES0402_0-5]  60.31 53.47 180 bottom
R622  10K  [RES0402_0-5]  147.32 53.02 270 bottom
R623  22E_1%  [RES0402]  60.31 52.05 0 bottom
R624  10K  [RES0402_0-5]  190.95 51.12 0 bottom
R625  49.9K_1%  [RES0402]  161.8 49.28 180 bottom
R626  1K  [RES0201]  126.03 49.26 270 bottom
R627  1K  [RES0201]  125.03 49.26 270 bottom
R628  1K  [RES0201]  124.03 49.26 270 bottom
R629  1K  [RES0201]  122.53 49.26 270 bottom
R630  10K  [RES0402_0-5]  147.57 48.41 0 bottom
R631  1K  [RES0201]  126.03 46.98 270 bottom
R632  1K  [RES0201]  125.03 46.98 270 bottom
R633  1K  [RES0201]  124.03 46.98 270 bottom
R634  1K  [RES0201]  122.53 46.98 270 bottom
R635  1K  [RES0201]  141.27 42.85 270 bottom
R636  1K  [RES0201]  140.27 42.85 270 bottom
R637  1K  [RES0201]  139.27 42.85 270 bottom
R638  1K  [RES0201]  137.77 42.85 270 bottom
R639  0E  [RES0402_0-5]  39.18 41.89 90 bottom
R640  0E  [RES0402_0-5]  37.91 41.89 90 bottom
R641  4.7K  [RES0402]  36.89 41.89 270 bottom
R642  1K  [RES0201]  141.27 40.94 270 bottom
R643  1K  [RES0201]  140.27 40.94 270 bottom
R644  1K  [RES0201]  139.27 40.94 270 bottom
R645  1K  [RES0201]  137.77 40.94 270 bottom
R646  0E  [RES0402_0-5]  37.91 40.11 270 bottom
R647  10K  [RES0402_0-5]  113.34 35.79 270 bottom
R648  10K  [RES0402_0-5]  144.74 35.08 180 bottom
R649  1K  [RES0201]  61.91 34.73 90 bottom
R650  1K  [RES0201]  60.9 34.73 270 bottom
R651  1K  [RES0201]  59.88 34.73 90 bottom
R652  1K  [RES0201]  58.86 34.73 270 bottom
R653  4.87K_1%  [RES0402]  57.85 34.73 90 bottom
R654  4.7K  [RES0402]  52.39 34.42 270 bottom
R655  4.7K  [RES0402]  51.37 34.42 270 bottom
R656  10K  [RES0402_0-5]  144.74 34.06 0 bottom
R657  51E  [RES0402]  63.56 31.31 90 bottom
R658  10K  [RES0402_0-5]  138.83 23.05 180 bottom
R659  10K  [RES0402_0-5]  83.31 20.7 270 bottom
R660  10K  [RES0402_0-5]  82.3 20.7 270 bottom
R661  10K  [RES0402_0-5]  81.28 20.7 90 bottom
R662  4.7K  [RES0402]  143.99 19.88 180 bottom
R663  4.7K  [RES0402]  40.01 19.73 0 bottom
R664  10K  [RES0402_0-5]  135.23 19.62 180 bottom
R665  0E  [RES0402_0-5]  63.94 18.52 0 bottom
R666  4.7K  [RES0402]  147.13 18.29 270 bottom
R667  10K  [RES0402_0-5]  76.71 18.01 180 bottom
R668  10K  [RES0402_0-5]  136.87 16.26 270 bottom
R669  10K  [RES0402_0-5]  135.85 16.26 90 bottom
R670  100E  [RES0402_0-5]  63.56 15.94 90 bottom
R671  10K  [RES0402_0-5]  130.31 15.71 90 bottom
R672  10K  [RES0402_0-5]  203.44 158.84 270 bottom
R673  10K  [RES0402_0-5]  203.41 160.98 90 bottom
R674  22E_1%  [RES0402]  136.23 14.68 0 bottom
R675  0E  [RES0402_0-5]  198.31 14.2 0 bottom
R676  0E  [RES0402_0-5]  146.54 14.17 180 bottom
R677  220K_1%  [RES0402_0-5]  64.58 14.16 90 bottom
R678  330K_1%  [RES0402_0-5]  63.56 14.16 270 bottom
R679  0E  [RES0402_0-5]  138.87 14.15 0 bottom
R680  10K  [RES0402_0-5]  202.25 160.98 90 bottom
R681  10K  [RES0402_0-5]  126.94 13.46 90 bottom
R682  10K  [RES0402_0-5]  125.92 13.46 90 bottom
R683  10K  [RES0402_0-5]  124.9 13.46 90 bottom
R684  10K  [RES0402_0-5]  123.89 13.46 90 bottom
R685  10K  [RES0402_0-5]  121.86 13.44 90 bottom
R686  10K  [RES0402_0-5]  77.57 13.25 180 bottom
R687  10K  [RES0402_0-5]  80.53 12.83 90 bottom
R688  10K  [RES0402_0-5]  143.57 11.44 270 bottom
R689  0E  [RES0402_0-5]  127.95 10.79 270 bottom
R690  0E  [RES0402_0-5]  126.94 10.79 270 bottom
R691  0E  [RES0402_0-5]  125.92 10.79 270 bottom
R692  0E  [RES0402_0-5]  124.9 10.79 270 bottom
R693  0E  [RES0402_0-5]  123.89 10.79 270 bottom
R694  0E  [RES0402_0-5]  122.87 10.79 270 bottom
R695  0E  [RES0402_0-5]  121.86 10.79 270 bottom
R696  4.7K  [RES0402]  120.84 10.79 270 bottom
R697  4.7K  [RES0402]  119.82 10.79 270 bottom
R698  10K  [RES0402_0-5]  73.97 9.82 180 bottom
R699  22E_1%  [RES0402]  165.46 7.67 180 bottom
R700  10K  [RES0402_0-5]  164.85 2.36 180 bottom
R701  49.9E_1%  [RES0201]  86.84 158.75 90 bottom
R702  0E  [RES0402_0-5]  85.82 158.89 90 bottom
R703  49.9E_1%  [RES0201]  86.67 117.33 270 bottom
R704  0E  [RES0402_0-5]  85.65 117.19 270 bottom
R705  0E  [RES0402_0-5]  150.5 150.37 0 bottom
R706  10E_1%  [RES0402_0-5]  149.19 135.08 90 bottom
R707  10K  [RES0402_0-5]  204.88 162.88 270 bottom
R708  10E_1%  [RES0402_0-5]  132.84 153.67 0 bottom
R709  10E_1%  [RES0402_0-5]  131.06 153.67 180 bottom
R710  10E_1%  [RES0402_0-5]  148.46 156.21 180 bottom
R711  10E_1%  [RES0402_0-5]  151.77 156.21 0 bottom
R712  10E_1%  [RES0402_0-5]  184.53 156.84 180 bottom
R713  10E_1%  [RES0402_0-5]  186.31 156.84 0 bottom
R714  10E_1%  [RES0402_0-5]  112.65 103.25 180 bottom
R715  10E_1%  [RES0402_0-5]  114.55 103.25 0 bottom
R716  10E_1%  [RES0402_0-5]  181.99 69.47 270 top
R717  10E_1%  [RES0402_0-5]  181.99 71.25 90 top
R718  10E_1%  [RES0402_0-5]  152.27 166.24 90 bottom
R719  10E_1%  [RES0402_0-5]  152.27 164.47 270 bottom
R720  10E_1%  [RES0402_0-5]  165.74 151.13 0 bottom
R721  10E_1%  [RES0402_0-5]  163.96 151.13 180 bottom
R722  10E_1%  [RES0402_0-5]  173.1 151.38 180 bottom
R723  10E_1%  [RES0402_0-5]  176.91 151.38 0 bottom
R724  22E_1%  [RES0402]  135.21 140.72 270 top
R725  22E_1%  [RES0402]  136.22 140.72 270 top
R726  22E_1%  [RES0402]  136.02 151.26 90 top
R727  22E_1%  [RES0402]  137.03 151.26 90 top
R728  0E  [RES0402_0-5]  177.17 117.86 180 top
R729  0E  [RES0402_0-5]  146.46 141.17 90 top
R730  10K  [RES0402_0-5]  185.93 82.04 270 bottom
R731  10K  [RES0402_0-5]  185.67 83.95 0 bottom
R732  10K  [RES0402_0-5]  149.24 127.38 270 bottom
R735  10K  [RES0402_0-5]  183.13 63.88 0 bottom
R736  10K  [RES0402_0-5]  185.55 59.44 270 bottom
R737  10K  [RES0402_0-5]  67.01 102.62 90 bottom
R738  10K  [RES0402_0-5]  75.34 106.5 90 bottom
R739  10K  [RES0402_0-5]  177.42 69.6 270 bottom
R740  10K  [RES0402_0-5]  176.4 69.6 270 bottom
R741  10K  [RES0402_0-5]  175.51 69.6 90 bottom
R742  39.2E_1%  [RES0402]  195.07 134.62 0 bottom
R743  0E  [RES0402_0-5]  150.5 151.38 0 bottom
R745  0E  [RES0402_0-5]  143.51 136.78 180 bottom
RA1  0E  [RESA_0402-8]  115.85 98.35 90 top
RA2  22E  [RESA_EXB28V_0402-4_0-5]  131.57 94.23 270 top
RA3  0E  [RESA_0402-8]  115.85 93.58 90 top
RA4  22E  [RESA_EXB28V_0402-4_0-5]  131.57 88.96 270 top
RA5  0E  [RESA_0402-8]  115.85 88.76 90 top
RA6  0E  [RESA_EXBN8V_0402-4_0-6]  170.4 67.88 90 top
RA7  22E  [RESA_EXB28V_0402-4_0-5]  151.89 120.55 0 bottom
RA8  22E  [RESA_0402-8]  145.29 120.55 0 bottom
RA9  0E  [RESA_0402-8]  115.85 98.35 270 bottom
RA10  0E  [RESA_0402-8]  115.85 93.58 270 bottom
RA11  0E  [RESA_0402-8]  115.85 88.76 270 bottom
RA12  22E  [RESA_EXB28V_0402-4_0-5]  123.63 87.76 90 bottom
RA13  22E  [RESA_EXB28V_0402-4_0-5]  123.63 84.71 90 bottom
RA14  22E  [RESA_0402-8]  161.16 72.07 0 bottom
RA15  22E  [RESA_EXB28V_0402-4_0-5]  151 74.3 180 bottom
RA16  22E  [RESA_EXB28V_0402-4_0-5]  134.37 74.3 180 bottom
RA17  0E  [RESA_EXBN8V_0402-4_0-6]  170.4 67.88 90 bottom
SW1  ATE1D-6M3-10-Z  [SW3_ATE1F-6M3_370X710_TH_5-6]  66.1 167.67 180 top
SW2  218-10LPST  [SW10_50_550X230_SMD]  143.37 59.77 90 top
SW3  218-10LPST  [SW10_50_550X230_SMD]  124.9 59.75 90 top
SW4  CHS-02TA_2PST  [SW2_50X200_160X210_SMD]  132.77 49.57 270 top
SW5  SKHMQLE010  [SW4_SKHMQLE010_240X260_SMD_3-1]  161.99 30.47 0 top
SW6  SKHMQLE010  [SW4_SKHMQLE010_240X260_SMD_3-1]  146.48 30.4 0 top
SW7  SKHMQLE010  [SW4_SKHMQLE010_240X260_SMD_3-1]  131.11 30.4 0 top
SW8  SKHMQLE010  [SW4_SKHMQLE010_240X260_SMD_3-1]  115.67 30.35 0 top
TP1  THRU HOLE  [TP_40X65]  112.78 172.09 0 top
TP2  5002  [TP_CIR67D40_TH_4-6]  75.06 168.91 180 bottom
TP3  -  [TP40_SMD]  141.73 170.43 180 top
TP4  5002  [TP_CIR67D40_TH_4-6]  206.5 129.03 0 top
TP5  THRU HOLE  [TP_40X65]  196.41 149.16 0 top
TP6  5002  [TP_CIR67D40_TH_4-6]  70.1 135.51 0 top
TP7  THRU HOLE  [TP_40X65]  120.46 140.42 0 top
TP8  -  [TP40_SMD]  177.61 138.35 0 top
TP9  THRU HOLE  [TP_40X65]  65.33 135.26 0 top
TP10  THRU HOLE  [TP_40X65]  33.42 130.86 0 top
TP11  -  [TP40_SMD]  177.61 124.64 180 top
TP12  -  [TP40_SMD]  31.88 120.59 0 top
TP13  -  [TP40_SMD]  177.61 110.92 180 top
TP14  -  [TP40_SMD]  34.04 107.95 0 top
TP15  -  [TP40_SMD]  177.61 97.21 180 top
TP16  -  [TP40_SMD]  45.56 95.17 0 top
TP17  -  [TP40_SMD]  47.75 95.12 0 top
TP18  -  [TP40_SMD]  177.61 83.49 180 top
TP19  THRU HOLE  [TP_40X65]  37.97 59.82 180 bottom
TP20  THRU HOLE  [TP_40X65]  118.06 39.56 0 top
TP21  5002  [TP_CIR67D40_TH_4-6]  130.84 37.45 0 top
TP22  THRU HOLE  [TP_40X65]  160.15 169.42 180 bottom
TP23  THRU HOLE  [TP_40X65]  130.43 172.85 180 bottom
TP24  THRU HOLE  [TP_40X65]  178.24 162.94 180 bottom
TP25  THRU HOLE  [TP_40X65]  140.53 161.86 180 bottom
TP26  THRU HOLE  [TP_40X65]  173.16 161.16 180 bottom
TP27  THRU HOLE  [TP_40X65]  120.9 159.96 180 bottom
TP28  -  [TP40_SMD]  152.78 147.45 180 bottom
TP29  -  [TP40_SMD]  166.43 124.65 0 bottom
TP30  -  [TP40_SMD]  164.15 124.65 270 bottom
TP31  -  [TP40_SMD]  161.86 124.65 0 bottom
TP32  -  [TP40_SMD]  159.58 124.65 0 bottom
TP34  -  [TP40_SMD]  165.35 122.62 0 bottom
TP35  -  [TP40_SMD]  163.07 122.62 0 bottom
TP36  -  [TP40_SMD]  160.78 122.62 0 bottom
TP37  -  [TP40_SMD]  158.5 122.62 0 bottom
TP38  -  [TP40_SMD]  138.37 120.27 270 bottom
TP39  -  [TP40_SMD]  172.02 117.09 270 bottom
TP40  -  [TP40_SMD]  120.59 115 90 bottom
TP41  -  [TP40_SMD]  174.56 115.82 270 bottom
TP42  -  [TP40_SMD]  172.02 114.55 270 bottom
TP43  -  [TP40_SMD]  120.52 112.46 270 bottom
TP44  -  [TP40_SMD]  174.56 113.28 270 bottom
TP45  -  [TP40_SMD]  172.02 112.01 270 bottom
TP46  -  [TP40_SMD]  174.56 110.74 270 bottom
TP47  -  [TP40_SMD]  120.52 110.24 270 bottom
TP48  -  [TP40_SMD]  172.02 109.46 270 bottom
TP49  -  [TP40_SMD]  120.46 108.01 270 bottom
TP50  -  [TP40_SMD]  120.4 105.79 270 bottom
TP51  -  [TP40_SMD]  120.4 103.57 270 bottom
TP52  -  [TP40_SMD]  123.06 103.5 90 bottom
TP53  -  [TP40_SMD]  125.41 103.44 270 bottom
TP54  -  [TP40_SMD]  120.4 101.28 270 bottom
TP55  -  [TP40_SMD]  47.75 91.88 0 bottom
TP56  -  [TP40_SMD]  45.56 91.84 0 bottom
TP57  THRU HOLE  [TP_40X65]  169.35 83.12 270 bottom
TP58  -  [TP40_SMD]  129.29 82.93 270 bottom
TP59  -  [TP40_SMD]  172.02 83.19 270 bottom
TP60  -  [TP40_SMD]  172.02 80.9 270 bottom
TP61  -  [TP40_SMD]  169.42 80.52 270 bottom
TP62  -  [TP40_SMD]  171.01 78.93 270 bottom
TP64  THRU HOLE  [TP_40X65]  39.11 72.09 180 bottom
TP65  -  [TP40_SMD]  121.87 16.56 180 bottom
TP66  THRU HOLE  [TP_40X65]  89.03 160.08 0 top
TP67  -  [TP40_SMD]  193.93 16.32 270 bottom
TP68  -  [TP40_SMD]  196.66 16.32 270 bottom
TP69  -  [TP40_SMD]  157.97 150.86 180 bottom
TP70  -  [TP40_SMD]  154.82 150.86 180 bottom
TP71  -  [TP40_SMD]  94.11 59.25 180 bottom
TP72  -  [TP40_SMD]  94.11 61.53 180 bottom
TP73  -  [TP40_SMD]  130.24 145.67 180 bottom
TP74  -  [TP40_SMD]  130.18 147.96 180 bottom
TP75  -  [TP40_SMD]  171.77 57.48 180 bottom
TP76  -  [TP40_SMD]  43.18 133.1 180 bottom
TP79  -  [TP40_SMD]  189.1 175.07 180 bottom
TP80  -  [TP40_SMD]  126.54 169.93 180 bottom
TP81  -  [TP40_SMD]  151.83 171.3 180 bottom
TP82  THRU HOLE  [TP_40X65]  201.74 157.67 0 top
TP83  -  [TP40_SMD]  100.55 151.45 180 bottom
TP84  -  [TP40_SMD]  205.51 156.7 180 bottom
TP85  -  [TP40_SMD]  39.24 125.45 180 bottom
TP86  -  [TP40_SMD]  160.59 142.49 180 bottom
TP87  5002  [TP_CIR67D40_TH_4-6]  36.07 27.69 180 bottom
TP88  5002  [TP_CIR67D40_TH_4-6]  173.99 137.67 180 bottom
U1  TLV70718DQNR  [X2SON4_TLV71318P_40X40_0-4]  128.91 168.78 270 top
U2  INA226AIDGSR  [MSOP10_19-68_120X120_1-1]  154.29 165.29 180 top
U3  INA226AIDGSR  [MSOP10_19-68_120X120_1-1]  184.96 160.56 270 top
U4  TPD4S012DRYR  [SON6_19-68_40X60_PB_0-6]  15.06 159.19 0 top
U5  TPS73525DRVR  [SON6_25-59_85X85_0-8]  197.35 158.91 180 top
U6  SN74AVC4T245RSVR  [UQFN16_15-74_105X75_0-6]  114.58 156.43 0 top
U7  TCA9554APWR  [TSSOP16_25-59_205X180_1-2]  141.16 155.77 0 top
U8  SN74LVC2G157DCUR  [VSSOP8_19-68_85X95_0-9]  121.14 155.4 0 top
U9  24LC512-I/SN  [SOIC8_1-8]  157.73 153.88 270 top
U10  TPS51206DSQR  [DFN10_15-74_80X80_0-8]  202.88 150.3 0 top
U11  TPS2051BD  [SOIC8_1-8]  16.79 150.15 90 top
U12  SN74AVC4T245RSVR  [UQFN16_15-74_105X75_0-6]  114.58 149.91 0 top
U13  SI4442DY  [SOIC8_1-8]  90.96 146.67 90 top
U14  LM25118MH/NOPB  [ETSSOP20_25-59_260X180_1-1]  73.53 141.73 180 top
U15  TPD4E004DRYR  [SON6_19-68_60X45]  14.16 140.4 90 top
U16  MT40A1G8WE-083E:B  [FBGA78_31-49_320X480_1-2]  185.61 139.95 90 top
U17  SN74LVC1G32DBVR  [SOT23-5_1-5]  160.46 138.18 0 top
U18  SI4442DY  [SOIC8_1-8]  82.8 132.72 180 top
U19  SN74AVC4T245RSVR  [UQFN16_15-74_105X75_0-6]  110.49 129.21 0 top
U20  MT40A1G8WE-083E:B  [FBGA78_31-49_320X480_1-2]  185.61 126.24 90 top
U21  SN74AVC4T245RSVR  [UQFN16_15-74_105X75_0-6]  111.41 120.88 270 top
U22  DP83867IRRGZ  [QFN48_19-68_280X280_1]  37.08 115.39 0 top
U23  SN74LVC2G157DCUR  [VSSOP8_19-68_85X95_0-9]  111.42 115.11 180 top
U24  MT25QL128ABA8E12  [TPBGA24_39-37_240X320_1-2]  100.77 114.05 180 top
U25  MT40A1G8WE-083E:B  [FBGA78_31-49_320X480_1-2]  185.61 112.52 90 top
U26  TS3L110PWG4  [TSSOP16_25-59_205X180]  89.6 107.95 270 top
U27  INA226AIDGSR  [MSOP10_19-68_120X120_1-1]  114.28 106.6 270 top
U28  SN74LVC1G08DBVRE4  [SOT23-5]  102.29 106.58 180 top
U29  SN74AVC2T245RSWR  [QFN10_15-74_75X60]  31.88 104.9 0 top
U30  TXS0102DCUR  [VSSOP8_19-68_85X95_0-9]  39.34 104.9 180 top
U31  DP83867IRRGZ  [QFN48_19-68_280X280_1]  51.82 102.23 0 top
U32  CDCLVC1310RHBR  [QFN32_19-68_200X200_1]  71.88 98.81 90 top
U33  MT40A1G8WE-083E:B  [FBGA78_31-49_320X480_1-2]  185.61 98.81 90 top
U34  MAXWELL M4  [BGA784_31-49_910X910_1-7]  147.96 97.79 270 top
U35  TPS3711DDCR  [SOT23-6_1-1]  90.61 92.43 180 top
U36  SN74LVC1G04DCKR  [SC70-5]  85.05 86.41 90 top
U37  TXS0102DCUR  [VSSOP8_19-68_85X95_0-9]  91.07 85.99 270 top
U38  MT40A1G8WE-083E:B  [FBGA78_31-49_320X480_1-2]  185.61 85.09 90 top
U39  SN74LVC1G32DBVR  [SOT23-5_1-5]  99.25 78.09 0 top
U40  TPS62097RWKT  [VQFNHR11_TPS62097_80X80_1]  33.54 76.32 90 top
U41  SN74LVC1G32DBVR  [SOT23-5_1-5]  99.25 74.1 0 top
U42  SN74CB3Q3257PWR  [TSSOP16_25-59_205X180]  107 73.09 270 top
U43  SN74AVC4T245RGYR  [QFN16_19-68_160X140]  111.07 64.81 90 top
U44  TMP100NA/3K  [SOT23-6_1-5]  174.24 62.55 0 top
U45  TXS0102DCUR  [VSSOP8_19-68_85X95_0-9]  188.64 56.82 0 bottom
U46  TCA9554APWR  [TSSOP16_25-59_205X180_1-2]  89.08 61.65 270 top
U47  TPD6E001RSER  [UQFN10_19-68_80X60_0-6]  176.06 55 180 top
U48  SN74LVC1G08DBVRE4  [SOT23-5]  153.57 53.16 90 top
U49  TPS3897ADRYR  [SON6_19-68_40X60_0-6]  113.81 53.09 90 top
U50  SN74LVC1G11DCKR  [SC70-6]  107.69 53.06 270 top
U51  MTFC16GAKAEJP  [VFBGA153_19-68_460X520_1-2]  162.43 52.07 0 top
U52  SN74LVC3G17DCUR  [VSSOP8_19-68_85X95_0-9]  114.77 46.07 270 top
U53  SN74LVC1G08DBVRE4  [SOT23-5]  107.44 45.09 270 top
U54  SN74LVC3G17DCUR  [VSSOP8_19-68_85X95_0-9]  104.14 44.7 90 top
U55  SN74LVC1G08DBVRE4  [SOT23-5]  112.39 38.61 90 top
U56  AT24CM01  [TSSOP8_25-59_125X180_1-2]  181.93 16.95 0 top
U57  TPS79601DRBR  [SON8_25-59_130X130_1]  108.46 8.06 90 top
U58  TPD4E004DRYR  [SON6_19-68_60X45]  104.02 7.24 180 top
U59  TPS62363YZHT  [DSBGA16_19-68_80X80_0-7]  186.08 172.16 180 bottom
U60  LP5912-1.8DRVT  [SON6_25-59_85X85_0-8]  156.91 172.03 90 bottom
U61  TPS62480RNCT  [VQFNHR16_TPS62480_100X120_1]  141.1 170.94 0 bottom
U62  MIC5060YML  [DFN8_25-59_120X120_1]  62.91 169.91 180 bottom
U63  TPS62097RWKT  [VQFNHR11_TPS62097_80X80_1]  166.52 166.93 180 bottom
U64  TPS62095RGTR  [QFN16_19-68_120X120_1]  114.36 165.73 90 bottom
U65  SN74LVC2G157DCUR  [VSSOP8_19-68_85X95_0-9]  121.14 155.4 0 bottom
U66  LM5060MM  [MSOP10_19-68_120X120]  29.22 154.51 0 bottom
U67  INA226AIDGSR  [MSOP10_19-68_120X120_1-1]  149.65 153.85 180 bottom
U68  INA226AIDGSR  [MSOP10_19-68_120X120_1-1]  131.7 151.19 180 bottom
U69  INA226AIDGSR  [MSOP10_19-68_120X120_1-1]  175.05 149.02 180 bottom
U70  INA226AIDGSR  [MSOP10_19-68_120X120_1-1]  164.77 148.77 180 bottom
U71  CSD18543Q3A  [VSONP8_CSD18543Q_120X130_0-9]  82.62 143.67 90 bottom
U72  CSD18543Q3A  [VSONP8_CSD18543Q_120X130_0-9]  87.54 141.89 270 bottom
U73  FT4232HL  [LQFP64_19-68_390X390_1-6]  26.8 138.94 0 bottom
U74  SN74LVC1G08DBVRE4  [SOT23-5]  160.46 138.18 0 bottom
U75  LM5140QRWGTQ1  [QFN40_19-68_240X240_0-9]  103.2 137.12 90 bottom
U76  TPS73533DRVR  [SON6_25-59_85X85]  10.92 134.87 90 bottom
U77  MT35XU512ABA1G12-0SIT  [TPBGA24_39-37_240X320_1-2]  145.03 130.81 180 bottom
U78  CSD18543Q3A  [VSONP8_CSD18543Q_120X130_0-9]  87.54 132.18 90 bottom
U79  93LC46B  [MSOP8_25-59_125X125_1-1]  28.7 128.52 0 bottom
U80  TPS54334DRCT  [SON10_19-68_125X125_1]  46.74 128.78 180 bottom
U81  CSD18543Q3A  [VSONP8_CSD18543Q_120X130_0-9]  82.62 129.28 270 bottom
U82  SN74LVC1G08DBVRE4  [SOT23-5]  36.07 127.38 180 bottom
U83  SN74LVC2G157DCUR  [VSSOP8_19-68_85X95_0-9]  111.42 115.11 180 bottom
U84  TPIC2810D  [SOIC16_1-8]  63.41 113.09 270 bottom
U85  SN74AVC4T245RSVR  [UQFN16_15-74_105X75_0-6]  82.53 108.05 0 bottom
U86  SN74LVC1G08DBVRE4  [SOT23-5]  67.63 87.68 180 bottom
U87  TXS0102DCUR  [VSSOP8_19-68_85X95_0-9]  91.07 85.99 90 bottom
U88  DP83867IRRGZ  [QFN48_19-68_280X280_1]  51.82 84.77 0 bottom
U89  TMP100NA/3K  [SOT23-6_1-5]  147.57 78.74 0 bottom
U90  SN74LVC1G32DBVR  [SOT23-5_1-5]  99.25 78.09 0 bottom
U91  MCP79410-I/SN  [SOIC8_1-8]  88.65 78.8 0 bottom
U92  SN74LVC1G32DBVR  [SOT23-5_1-5]  99.25 74.1 0 bottom
U93  INA226AIDGSR  [MSOP10_19-68_120X120_1-1]  183.05 70.16 180 bottom
U94  TPS62087RLTR  [VSONHR7_TPS62085_80X80_1]  32.96 68.83 270 bottom
U95  SN74AVC4T245RGYR  [QFN16_19-68_160X140]  143.4 62.66 90 bottom
U96  TXS0102DCUR  [VSSOP8_19-68_85X95_0-9]  188.64 62.41 180 bottom
U97  SN74AVC2T244DQMR  [X2SON8_15-74_70X50]  42.79 59.4 180 bottom
U98  SN74AVC4T245RGYR  [QFN16_19-68_160X140]  56.51 52.3 270 bottom
U99  TCA6424ARGJR  [QFN32_19-68_200X200]  143.1 51.05 90 bottom
U100  TXB0108RGYR  [QFN20_19-68_185X145_1]  186.66 50.37 0 bottom
U101  SN74AVC2T244DQMR  [X2SON8_15-74_70X50]  56.79 46.24 270 bottom
U102  SN74AVC8T245RHL  [QFN24_19-68_220X140_1]  124.78 43.6 180 bottom
U103  TXS0102DCUR  [VSSOP8_19-68_85X95_0-9]  51.88 39 180 bottom
U104  SN74LVC1G08DBVRE4  [SOT23-5]  112.39 38.61 270 bottom
U105  SN74AVC8T245RHL  [QFN24_19-68_220X140_1]  140.02 37.57 180 bottom
U106  TM4C1294NCPDTT3R  [TQFP128_15-74_550X550_1-2]  54.29 24.32 0 bottom
U107  LM4040B25IDCKR  [SC70-5_1-1]  39.43 21.89 180 bottom
U108  SN74LVC1G08DBVRE4  [SOT23-5]  138.05 20.57 180 bottom
U109  SN74AVC2T245RSWR  [QFN10_15-74_75X60]  205.51 159.87 0 bottom
U110  TCA9555RTWR  [QFN24_19-68_165X165]  80.52 16.76 180 bottom
U111  TXS0108ERGYR  [QFN20_19-68_185X145_1]  142.82 15.93 270 bottom
U112  24MHz  [OSC4_KC2520B_100X80_SMD]  133.18 15.4 0 bottom
U113  SN74LVC1G08DBVRE4  [SOT23-5]  76.79 10.77 180 bottom
U114  24MHz  [OSC4_KC2520B_100X80_SMD]  165.16 5.1 90 bottom
U115  TPS2051BD  [SOIC8_1-8]  181.74 59.56 270 bottom
Y1  25MHz  [XTAL_ABM3_210X130_SMD]  83.5 98.18 270 top
Y2  12.000MHz  [XTAL_ABM3_205X130_SMD]  16.64 133.73 90 bottom
Y3  25MHz  [XTAL_ABM3_210X130_SMD]  124.78 108.3 90 bottom
Y4  24.576MHz  [XTAL4_TXC_130X100_SMD_0-8]  170.99 87.2 90 bottom
Y5  32.768KHz  [XTAL_ABS07_130X60_SMD_0-9]  78.68 77.53 270 bottom
Y6  16.000MHZ  [XTAL4_NX3225GA_130X100_SMD_0-9]  68.08 20.91 270 bottom

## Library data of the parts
B1 = BATTERY
C1-C11 C13-C23 C25 C26 C29-C38 C40-C53 C56 C57 C62-C71 C73-C83 C85-C92 C94-C117 C119-C151 C153-C190 C192-C282 C285-C298 C300-C366 C369-C677 C679-C693 C695 C696 = CAP
C12 C24 C39 C72 C283 C284 C299 C367 C368 = CAP_POL
